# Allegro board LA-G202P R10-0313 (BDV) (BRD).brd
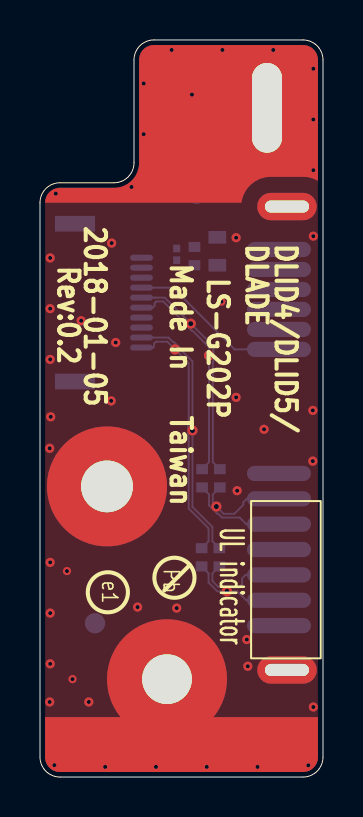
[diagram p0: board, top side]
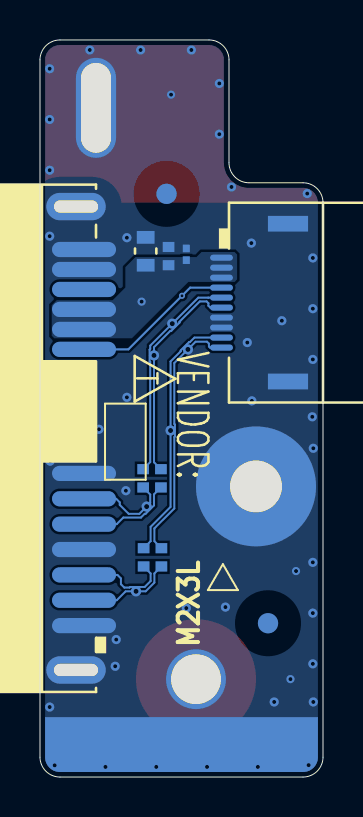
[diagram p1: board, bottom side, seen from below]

Outline 14.15 x 36.9 mm; copper layers: TOP, GND1, GND2, BOTTOM. Coordinates in mm from the lower left corner of the outline.
Outline path: 0,28.75 0,1 arc(0.29,0.29) 1,0 13.15,0 arc(13.86,0.29) 14.15,1 14.15,35.9 arc(13.86,36.61) 13.15,36.9 5.7,36.9 arc(4.99,36.61) 4.7,35.9 4.7,30.75 arc(4.41,30.04) 3.7,29.75 1,29.75 arc(0.29,29.46) 0,28.75

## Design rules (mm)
net group SATA_PRX_RC_DTX_1: nets SATA_PRX_RC_DTX_N1 SATA_PRX_RC_DTX_P1
net group SATA_PRX_RC_DTX_1_C: nets SATA_PRX_RC_DTX_N1_C SATA_PRX_RC_DTX_P1_C
net group SATA_PTX_RC_DRX_1: nets SATA_PTX_RC_DRX_N1 SATA_PTX_RC_DRX_P1
net group SATA_PTX_RC_DRX_1_C: nets SATA_PTX_RC_DRX_N1_C SATA_PTX_RC_DRX_P1_C
nets with their own width: min track width 0.508; nets +5V_ODD GND

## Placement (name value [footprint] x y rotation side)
C1  0.01U_0402_16V7K  [C_0402]  8.08 11.46 270 bottom
C2  0.01U_0402_16V7K  [C_0402]  8.97 11.46 270 bottom
C3  0.01U_0402_16V7K  [C_0402]  8.1 15.41 270 bottom
C4  0.01U_0402_16V7K  [C_0402]  8.99 15.41 270 bottom
C232  0.1U_0201_10V K X5R  [C_0201]  6.83 25.88 90 bottom
C237  1000P_0402_50V7K  [C_0402]  7.72 25.62 90 bottom
C238  10U_0603_6.3V6M  [C_0603]  8.87 25.62 90 bottom
FD1  CF  [FIDUCIAL_C40M80]  7.82 29.2 180 bottom
FD2  CF  [FIDUCIAL_C40M80]  2.75 7.7 180 bottom
H1  HOLEA  [H_2P6]  3.35 14.55 0 top
H2  HOLEA  [H_2P5]  6.35 4.9 0 top
H3  HOLEA  [H_1P5X4P5]  11.35 33.5 0 top
JODD1  ACES_51530-01001-P01  [ACES_51530-01001-P01_10P]  5.08 26 90 bottom
JODD2  SANTA_201501-2  [SANTA_201501-2_13P]  11.95 7.58 270 bottom
NOREF  -  []  -9.27 -71.97 0 top
NOREF#2  -  []  14.15 0 0 top
NOREF#3  -  []  -57.02 20.56 0 top
NOREF#4  -  []  14.15 0 0 top
NOREF#5  -  []  -11.45 25.93 0 top
NOREF#6  -  []  3.35 14.55 0 top
NOREF#7  -  []  6.61 26.86 270 top
NOREF#8  -  []  -6.17 6.58 180 bottom
NOREF#9  -  []  -36.62 -27.6 180 bottom

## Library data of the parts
C1-C4 C237 = C_0402
C232 = C_0201
C238 = C_0603
FD1 FD2 = FIDUCIAL_C40M80
H1 = H_2P6
H2 = H_2P5
H3 = H_1P5X4P5
JODD1 = ACES_51530-01001-P01_10P
JODD2 = SANTA_201501-2_13P

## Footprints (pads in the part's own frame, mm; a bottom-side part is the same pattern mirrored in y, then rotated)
ACES_51530-01001-P01_10P
  oval 0.305x1.143 smd: 1(0,0) 2(-0.5,0) 3(-1,0) 4(-1.5,0) 5(-2,0) 6(-2.5,0) 7(-3,0) 8(-3.5,0) 9(-4,0) 10(-4.5,0)
  rect 0.787x2.007 smd: 11(1.7,-3.325) 12(-6.2,-3.325)
C_0201
  rect 0.381x0.356 smd: 1(0,0) 2(0.584,0)
C_0402
  rect 0.508x0.584 smd: 1(0,0) 2(0.914,0)
C_0603
  rect 0.635x0.889 smd: 1(0,0) 2(1.397,0)
FIDUCIAL_C40M80
  round 1.016 smd: 1(0,0)
H_1P5X4P5
  oval 2.007x5.004 hole 1.499x4.496: 1(0,0)
H_2P5
  round 2.997 hole 2.489: 1(0,0)
H_2P6
  round 3.099 hole 2.591: 1(0,0)
SANTA_201501-2_13P
  oval 0.762x3.2 smd: 1(0,0) 2(-1.27,0) 3(-2.54,0) 4(-3.81,0) 5(-5.08,0) 6(-6.35,0) 7(-7.62,0) 8(-13.83,0) 9(-14.83,0) 10(-15.83,0) 11(-16.83,0) 12(-17.83,0) 13(-18.83,0)
  oval 1.372x2.972 hole 0.61x2.21: 14(-20.98,-0.4) 15(2.22,-0.4)

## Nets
+5V_ODD: C232.1 C237.1 C238.1 JODD1.1 JODD1.2 JODD1.3 JODD2.9 JODD2.10
GND: C232.2 C237.2 C238.2 H1.1(TP-1) H2.1(TP-1) H3.1(TP-1) JODD1.7 JODD1.8 JODD1.11 JODD1.12 JODD2.1 JODD2.4 JODD2.7 JODD2.12 JODD2.13 JODD2.14 JODD2.15
HDD_ODD_DETECT: JODD1.4 JODD2.8
SATA_PRX_RC_DTX_N1: C3.1 JODD1.6
SATA_PRX_RC_DTX_N1_C: C3.2 JODD2.5
SATA_PRX_RC_DTX_P1: C4.1 JODD1.5
SATA_PRX_RC_DTX_P1_C: C4.2 JODD2.6
SATA_PTX_RC_DRX_N1: C2.1 JODD1.9
SATA_PTX_RC_DRX_N1_C: C2.2 JODD2.3
SATA_PTX_RC_DRX_P1: C1.1 JODD1.10
SATA_PTX_RC_DRX_P1_C: C1.2 JODD2.2

Pads without a net: FD1 1; FD2 1; JODD2 11

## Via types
v1: diameter 0.305, hole 0.152, TOP to BOTTOM, 1 via
v2: diameter 0.508, hole 0.254, TOP to BOTTOM, 6 vias
v3: diameter 0.457, hole 0.203, TOP to BOTTOM, 42 vias
v4: diameter 0.406, hole 0.203, TOP to BOTTOM, 4 vias

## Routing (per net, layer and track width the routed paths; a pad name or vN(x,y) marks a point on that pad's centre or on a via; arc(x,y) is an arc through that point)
+5V_ODD:
  vias: v4(9.07,23.8)
GND: length 123.1
  GND1 w0.203: H1.1 5.08,14.55 ; H1.1 2.08,15.82 ; H1.1 4.62,15.82 ; H1.1 4.62,13.28 ; H1.1 3.35,16.28 ; H1.1 1.62,14.55 ; H1.1 2.08,13.28 ; H1.1 3.35,12.82 ; 10.68,6.22 JODD2.15 ; JODD2.15 10.68,5.36 ; JODD2.15 10.68,4.5 ; JODD2.15 12.35,6.22 ; JODD2.15 12.35,4.5 ; 5.11,3.66 H2.1 ; H2.1 7.59,3.66 ; H2.1 6.35,6.58 ; H2.1 4.67,4.9 ; H2.1 7.59,6.14 ; H2.1 8.03,4.9 ; H2.1 6.35,3.22 ; H2.1 5.11,6.14 ; 11.35,30.82 H3.1 ; H3.1 12.53,36.18 ; H3.1 10.17,30.82 ; H3.1 11.35,36.18 ; H3.1 10.17,36.18 ; H3.1 12.53,30.82 ; H3.1 10.17,33.5 ; H3.1 12.53,33.5 ; JODD2.14 12.35,29.42 ; JODD2.14 10.68,29.42 ; JODD2.14 12.35,27.7 ; JODD2.14 10.68,27.7 ; JODD2.14 10.68,28.56
  GND2 w0.203: 12.35,4.5 JODD2.15 ; JODD2.15 10.68,6.22 ; JODD2.15 10.68,4.5 ; JODD2.15 12.35,6.22 ; JODD2.15 10.68,5.36 ; 10.68,29.42 JODD2.14 ; JODD2.14 12.35,29.42 ; JODD2.14 12.35,27.7 ; JODD2.14 10.68,28.56 ; JODD2.14 10.68,27.7 ; 5.11,6.14 H2.1 ; H2.1 5.11,3.66 ; H2.1 7.59,6.14 ; H2.1 4.67,4.9 ; H2.1 8.03,4.9 ; H2.1 6.35,3.22 ; H2.1 7.59,3.66 ; H2.1 6.35,6.58 ; H3.1 12.53,33.5 ; H3.1 11.35,36.18 ; H3.1 10.17,30.82 ; H3.1 10.17,36.18 ; H3.1 12.53,36.18 ; H3.1 10.17,33.5 ; H3.1 12.53,30.82 ; H3.1 11.35,30.82 ; 1.62,14.55 H1.1 ; H1.1 3.35,12.82 ; H1.1 4.62,15.82 ; H1.1 3.35,16.28 ; H1.1 2.08,15.82 ; H1.1 2.08,13.28 ; H1.1 4.62,13.28 ; H1.1 5.08,14.55
  vias: v3(0.48,16.46) v3(0.48,3.76) v3(0.51,25.99) v3(0.51,23.45) v3(0.51,20.91) v3(0.54,18.03) v3(0.51,10.75) v3(0.51,8.21) v3(0.51,5.67) v3(0.79,29.21) v3(0.72,0.6) v3(2.06,22.84) v3(2.44,3.76) v3(3.26,0.51) v3(3.58,26.73) v3(3.56,18.83) v3(3.79,21.75) v3(4.57,29.54) v3(4.88,8.51) v3(5.18,34.72) v3(5.18,32.18) v3(5.8,0.51) v3(6.58,36.4) v3(6.83,8.46) v3(8.34,0.51) v3(9.12,36.4) v3(9.81,27) v3(9.81,19.01) v3(9.86,14.33) v3(10.34,6.88) v3(10.39,5.55) v3(10.88,0.51) v3(11.2,17.41) v3(11.66,36.4) v3(13.42,0.59) v3(13.67,35.46) v3(13.67,32.92) v3(13.67,30.38) v3(13.67,27.08) v3(13.64,18.36) v3(13.64,15.82) v3(13.67,3.51) v4(1.35,10.31) v4(1.63,4.9) v4(7.6,34.16)
HDD_ODD_DETECT: length 8.2
  BOTTOM w0.102: JODD2.8 9.73,21.41 v1(7.05,24.09) 6.64,24.5 JODD1.4
SATA_PRX_RC_DTX_N1: length 11.1
  BOTTOM w0.097: 5.02,23.5 4.93,23.5 4.93,23.5 JODD1.6 5.63,23.5 5.73,23.59 5.73,23.72 5.82,23.81 6.16,23.81 7.17,22.79 7.17,22.75 7.59,22.34 7.63,22.34 8.45,21.52 v2(8.45,21.11) 8.45,15.76 C3.1
SATA_PRX_RC_DTX_N1_C: length 4.9
  BOTTOM w0.097: C3.2 8.45,14.15 8.45,13.6 8.87,13.18 8.91,13.18 9.1,12.99 9.98,12.99 10.31,12.66 JODD2.5
SATA_PRX_RC_DTX_P1: length 11.2
  BOTTOM w0.097: C4.1 8.64,15.77 8.64,20.78 8.67,20.82 8.67,21.4 8.64,21.43 8.64,21.6 v2(7.54,22.7) 6.24,24 5.74,24 5.74,24 JODD1.5 4.93,24 4.93,24 5.02,24
SATA_PRX_RC_DTX_P1_C: length 4.8
  BOTTOM w0.097: C4.2 8.64,14.14 8.64,13.72 v2(8.82,13.54) 9.18,13.18 9.72,13.18 10.16,13.62 10.16,13.75 10.34,13.93 JODD2.6
SATA_PTX_RC_DRX_N1: length 13
  BOTTOM w0.097: JODD1.9 6.43,22 6.66,21.77 6.7,21.77 7.12,21.36 7.12,21.31 7.62,20.81 v2(7.62,17.35) 7.62,13.52 8.62,12.53 8.62,11.81 C2.1
SATA_PTX_RC_DRX_N1_C: length 4.8
  BOTTOM w0.097: C2.2 8.62,10.19 8.62,9.81 8.91,9.52 9.64,9.52 9.67,9.49 9.93,9.49 10.1,9.66 10.1,9.95 10.28,10.12 JODD2.3
SATA_PTX_RC_DRX_P1: length 12.9
  BOTTOM w0.097: JODD1.10 5.65,21.5 5.7,21.55 5.7,21.7 5.8,21.79 6.37,21.79 v2(6.75,21.41) 7.43,20.73 7.43,17.67 7.4,17.64 7.4,17.06 7.43,17.02 7.43,13.45 8.43,12.45 8.43,11.81 C1.1
SATA_PTX_RC_DRX_P1_C: length 4.8
  BOTTOM w0.097: C1.2 8.43,10.19 8.43,9.73 8.87,9.3 v2(9.35,9.3) 9.87,9.3 10.31,8.85 JODD2.2

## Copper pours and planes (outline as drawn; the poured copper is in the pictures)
+5V_ODD on BOTTOM: 4.42,26.28 6.07,26.28 6.33,26.03 9.37,26.03 9.88,25.52 9.88,24.51 10.52,23.87 13.31,23.87 13.57,23.62 13.57,22.09 13.44,21.97 9.55,21.97 6.73,24.79 4.42,24.79 4.29,24.91 4.29,26.16
GND on TOP, GND1, GND2: 1,0.25 0.47,0.47 0.25,1 0.25,28.75 0.47,29.28 1,29.5 3.7,29.5 4.59,29.86 4.95,30.75 4.95,35.9 5.17,36.43 5.7,36.65 13.15,36.65 13.68,36.43 13.9,35.9 13.9,1 13.68,0.47 13.15,0.25
GND on BOTTOM: 1,0.25 0.47,0.47 0.25,1 0.25,28.75 0.47,29.28 1,29.5 3.7,29.5 4.59,29.86 4.95,30.75 4.95,35.9 5.17,36.43 5.7,36.65 13.15,36.65 13.68,36.43 13.9,35.9 13.9,1 13.68,0.47 13.15,0.25 ; 1 cut-out

Small or netless copper shapes (teardrops, artwork), in the pictures only: 3 on TOP, 2 on BOTTOM

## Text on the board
Ref Des/Silkscreen Bottom: M2X3L
User.Comments: DLID4/DLID5/DLADE | LSG202P | 2019-01-05 | 2018-01-05 | Devil
Ref Des/Silkscreen Top: Taiwan | LS-G202P | DLADE
PAGE_OUTLINE: LAYER | NAME | L3 | L2 | L4 | L5 | L1 | L6 | LA-D708P | DUMMY-COOPER | BOT(50 ohm) | GND1 | GND2 | LS-C701P | TOP | BOT(90 ohm) | LS-C703P | VCC | GND | L7 | L9 | L8 | L10 | L11 | L12 | L13 | L14 | LA-XXXXP | LS-XXXXP | LA-D581P | LA-C602P | LA-D751P | IN1(50 ohm) | LS-C706P | IN2(85 ohm) | BOT | LS-D581P | LS-C601P | LS-D751P | IN1 | LS-D701P | TOP(50 ohm) | LS-D582P | LS-C602P | LS-D752P | IN2 | GND3 | IN3 | IN2(50,85 ohm) | BOT(50,85 ohm) | LS-D702P | LS-D754P | BOT(85 ohm) | TOP(85 ohm) | LS-C603P | LS-D757P | LS-D758P | TOP(50,85 ohm) | LS-D759P | GND4 | LS-D75AP | LS-D75BP | LS-D75CP | LS-D75DP
User.32: GND4
User.33: GND5
User.35: FIGURE | SIZE | 8.0 | 102.0 | 87.0x24.0 | 126.0x98.0 | 146.0x106.0 | DRILL CHART: TOP to BOTTOM | ALL UNITS ARE IN MILS | TOLERANCE | +3.0/-3.0 | PLATED | QTY | 39 | 1 | 2
User.36: Width/Space | L5-GND2 | L6-BOT | HR_1_0mm-6L(4mil  5mil 50ohm)_171122 | 4 mil | 3.8/3.6 | 85 ohm | L2 | Ref | L5
